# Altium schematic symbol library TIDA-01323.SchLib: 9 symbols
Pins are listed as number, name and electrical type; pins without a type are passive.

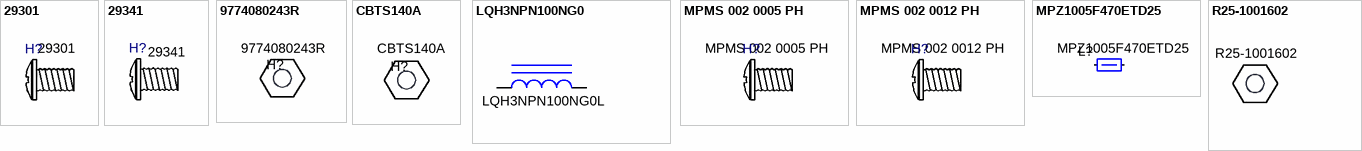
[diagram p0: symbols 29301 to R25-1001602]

## 29301
designator H?
MACHINE SCREW PAN SLOTTED M2.5; Manufacturer: Keystone Electronics; Screw Head Type: Pan Head; Thread Size: M2.5x0.45; Head Diameter: 0.189" (4.80mm); Head Height: 0.055" (1.40mm); Plating: Zinc, Clear Chromate
footprint 29301 (Footprint not found)

## 29341
designator H?
MACHINE SCREW PAN SLOTTED M3; Manufacturer: Keystone Electronics; Screw Head Type: Pan Head; Thread Size: M3x0.5; Head Diameter: 0.213" (5.40mm); Head Height: 0.067" (1.70mm)
footprint 29341 (Footprint not found)

## 9774080243R
designator H?
ROUND STANDOFF M2 STEEL 8MM; Manufacturer: Wurth Electronics Inc; Threaded/Unthreaded: Threaded; Between Board Height: 0.315" (8.00mm); Plating: Tin
footprint 9774080243R (Footprint not found)

## CBTS140A
designator H?
HEX STANDOFF M3 NYLON 40MM; Manufacturer: Essentra Components; Threaded/Unthreaded: Threaded; Gender: Female, Female; Between Board Height: 1.575" (40.00mm)
footprint CBTS140A (Footprint not found)

## LQH3NPN100NG0
designator L?, comment LQH3NPN100NG0L
FIXED IND 10UH 630MA 570 MOHM; Manufacturer: Murata Electronics North America; Type: Wirewound; Material - Core: Ferrite; Tolerance_%: ±30%; Current - Saturation: 500mA; Shielding: Shielded; DCR_Ohm: 684 mOhm Max; Frequency - Self Resonant: 45MHz; Frequency - Test: 1MHz; ValueDisplayed: 10µH
footprint ADL3225V (Footprint not found)
pins: 1, 2

## MPMS 002 0005 PH
designator H?
MACHINE SCREW PAN PHILLIPS M2; Manufacturer: B&F Fastener Supply; Screw Head Type: Pan Head; Head Diameter: 0.152" (3.85mm); Head Height: 0.060" (1.52mm); Plating: Zinc
footprint MPMS 002 0005 PH (Footprint not found)

## MPMS 002 0012 PH
designator H?
MACHINE SCREW PAN PHILLIPS M2; Manufacturer: B&F Fastener Supply; Screw Head Type: Pan Head; Head Diameter: 0.152" (3.85mm); Head Height: 0.060" (1.52mm); Plating: Zinc
footprint MPMS 002 0012 PH (Footprint not found)

## MPZ1005F470ETD25
designator L?
FERRITE BEAD 47 OHM 0402 1LN with 0603 foorprint; Manufacturer: TDK Corporation; CompType: Used in BOM report; Filter Type: Power Line; Number of Lines: 1; Impedance @ Frequency: 47 Ohm @ 100MHz; Current Rating (Max): 450mA; DC Resistance (DCR) (Max): 450 mOhm
footprint 0603 (Footprint not found)
pins: 1, 2

## R25-1001602
designator H?
HEX STANDOFF M2.5 BRASS 16MM; Manufacturer: Harwin Inc.; Threaded/Unthreaded: Threaded; Gender: Female, Female; Screw, Thread Size: M2.5x0.45; Between Board Height: 0.630" (16.00mm); Plating: Nickel
footprint R25-1001602 (Footprint not found)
